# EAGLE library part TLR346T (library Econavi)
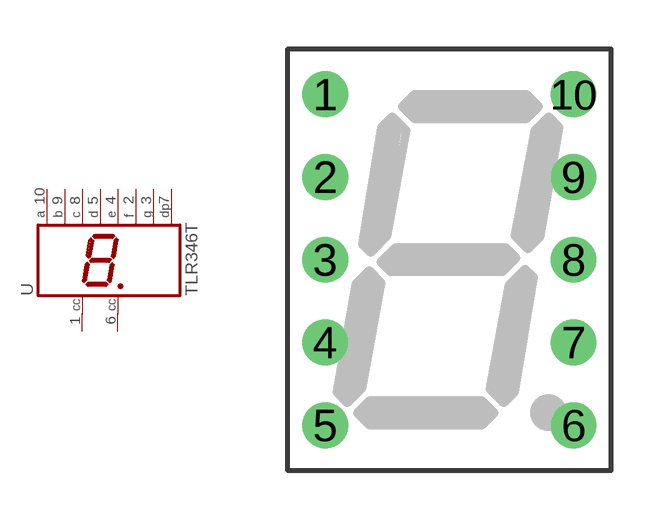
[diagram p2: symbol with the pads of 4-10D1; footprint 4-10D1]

Designator prefix -

## TLR346T  [4-10D1]
1  CA  pas
2  F  pas
3  G  pas
4  E  pas
5  D  pas
6  CA  pas
7  DP  pas
8  C  pas
9  B  pas
10  A  pas

## Footprint 4-10D1 (pad centres in mm)
LED DISPLAY 10-mm 1 character 7 segment, decimal point right
drill 0.9 round: 1 -3.81,5.08; 2 -3.81,2.54; 3 -3.81,0; 4 -3.81,-2.54; 5 -3.81,-5.08; 6 3.81,-5.08; 7 3.81,-2.54; 8 3.81,0; 9 3.81,2.54; 10 3.81,5.08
